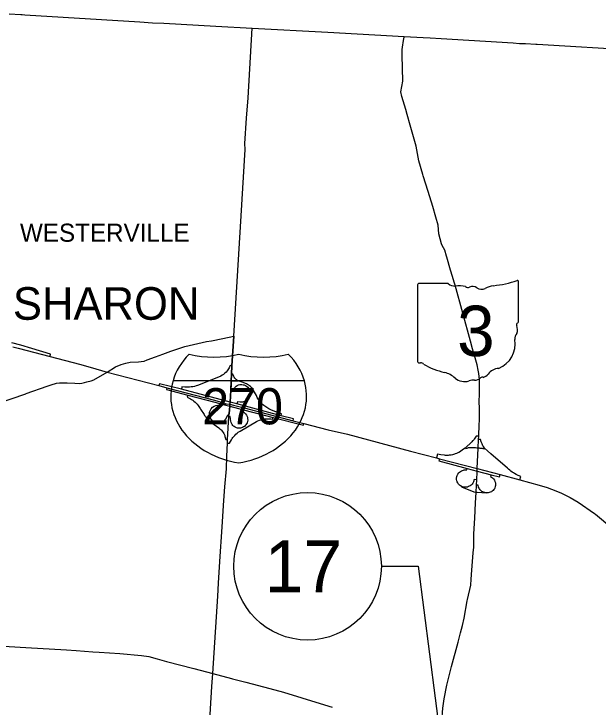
# Model space of a CAD drawing. Extents: x -1146 to -445, y -1283 to -822.
# Drawn here: x -863.1 to -822.78, y -948.44 to -900.58 of the extents above; entities that cross this region are included whole.
import ezdxf

# ---------------------------------------------------------------- set-up
doc = ezdxf.new("R2010")
doc.units = 0
for name, color, linetype in [('Default', 7, 'Continuous'), ('GM_X_Corporation_Text', 7, 'Continuous'), ('GM_X_County', 7, 'Continuous'), ('GM_X_Interchange_Ramps', 7, 'Continuous'), ('GM_X_Interstate_Route', 7, 'Continuous'), ('GM_X_Interstate_Shield', 7, 'Continuous'), ('GM_X_State_Route', 7, 'Continuous'), ('GM_X_State_Shield', 7, 'Continuous'), ('GM_X_Township', 7, 'Continuous'), ('GM_X_Township_Text', 7, 'Continuous')]:
    doc.layers.add(name, color=color, linetype=linetype)

msp = doc.modelspace()

# ---------------------------------------------------------------- linework, layer by layer
at = {"layer": 'Default'}
msp.add_lwpolyline([(-837.735, -938.717), (-835.188, -938.717), (-833.622, -950.863)], dxfattribs=at)
msp.add_circle((-842.83, -938.717), 5.094, dxfattribs=at)
at = {"layer": 'GM_X_County'}
msp.add_lwpolyline([(-863.427, -900.578), (-862.623, -900.623), (-862.528, -900.628), (-862.344, -900.639), (-854.414, -901.127), (-853.529, -901.186), (-852.746, -901.23), (-849.162, -901.431), (-846.653, -901.557), (-841.434, -901.832), (-836.157, -902.132), (-834.842, -902.215), (-834.367, -902.243), (-833.605, -902.289), (-828.634, -902.589), (-828.197, -902.613), (-827.798, -902.635), (-827.073, -902.676), (-826.986, -902.681), (-820.114, -903.073)], dxfattribs=at)
at = {"layer": 'GM_X_Interchange_Ramps'}
for points in [[(-860.593, -924.234), (-860.567, -924.06), (-861.86, -923.684), (-862.612, -923.457), (-863.25, -923.291)], [(-848.052, -924.87), (-848.177, -924.863), (-848.209, -924.943), (-848.243, -925.012), (-848.287, -925.09), (-848.329, -925.154), (-848.387, -925.232), (-848.452, -925.307), (-848.535, -925.388), (-848.626, -925.463), (-848.714, -925.523), (-848.826, -925.586), (-848.981, -925.652), (-850.419, -926.232), (-850.519, -926.264), (-850.629, -926.293), (-850.753, -926.319), (-850.854, -926.335), (-850.979, -926.348), (-851.067, -926.354), (-851.178, -926.355), (-851.292, -926.352), (-851.498, -926.335), (-851.537, -926.479)], [(-844.655, -928.316), (-844.621, -928.179), (-845.024, -928.046), (-845.317, -927.928), (-845.507, -927.841), (-845.712, -927.716), (-845.786, -927.663), (-845.853, -927.609), (-845.93, -927.541), (-846.005, -927.467), (-846.056, -927.411), (-846.115, -927.34), (-846.162, -927.278), (-846.216, -927.2), (-846.261, -927.127), (-846.3, -927.058), (-846.332, -926.993), (-846.359, -926.935), (-846.566, -926.57), (-846.596, -926.517), (-846.636, -926.456), (-846.679, -926.402), (-846.737, -926.338), (-846.78, -926.297), (-846.829, -926.256), (-846.885, -926.215), (-846.933, -926.184), (-846.986, -926.155), (-847.047, -926.125), (-847.103, -926.103), (-847.167, -926.083), (-847.592, -925.91), (-847.657, -925.879), (-847.706, -925.85), (-847.756, -925.812), (-847.802, -925.771), (-847.842, -925.727), (-847.885, -925.669), (-847.912, -925.622), (-847.989, -925.457), (-848.085, -925.452)], [(-847.592, -925.91), (-847.603, -925.937), (-848.009, -925.932), (-848.102, -925.932)], [(-843.829, -928.663), (-843.799, -928.545), (-844.655, -928.316), (-847.713, -927.5), (-848.18, -927.375), (-851.537, -926.479), (-853.054, -926.112), (-853.088, -926.242)], [(-852.537, -926.385), (-852.571, -926.513), (-851.09, -926.899), (-849.224, -927.385), (-848.65, -927.535), (-848.202, -927.652), (-847.244, -927.903), (-845.211, -928.435), (-843.118, -928.982), (-843.085, -928.854)], [(-848.124, -926.56), (-847.985, -926.569), (-847.906, -926.442), (-847.868, -926.389), (-847.813, -926.326), (-847.761, -926.276), (-847.692, -926.232), (-847.607, -926.195), (-847.51, -926.17), (-847.442, -926.162), (-847.374, -926.162), (-847.27, -926.177), (-847.197, -926.198), (-847.109, -926.238), (-847.038, -926.285), (-846.961, -926.354), (-846.887, -926.451), (-846.836, -926.554), (-846.811, -926.639), (-846.797, -926.743), (-846.802, -926.859), (-846.826, -926.961), (-846.865, -927.054), (-846.914, -927.132), (-846.96, -927.188), (-847.031, -927.253), (-847.104, -927.302), (-847.167, -927.333), (-847.252, -927.362), (-847.332, -927.377), (-847.478, -927.38), (-847.675, -927.366), (-847.713, -927.5)], [(-851.09, -926.899), (-851.129, -927.048), (-850.997, -927.103), (-850.912, -927.151), (-850.832, -927.201), (-850.754, -927.255), (-850.679, -927.313), (-850.596, -927.385), (-850.527, -927.45), (-850.453, -927.53), (-850.383, -927.614), (-850.338, -927.673), (-850.286, -927.749), (-850.244, -927.816), (-850.211, -927.874), (-849.975, -928.231), (-849.933, -928.301), (-849.885, -928.372), (-849.842, -928.431), (-849.777, -928.51), (-849.714, -928.58), (-849.654, -928.641), (-849.581, -928.707), (-849.515, -928.761), (-849.436, -928.821), (-849.37, -928.865), (-849.273, -928.923), (-848.947, -929.165), (-848.883, -929.217), (-848.825, -929.271), (-848.772, -929.327), (-848.716, -929.395), (-848.662, -929.472), (-848.615, -929.551), (-848.574, -929.633), (-848.551, -929.687), (-848.53, -929.744), (-848.509, -929.814), (-848.476, -929.954), (-848.351, -929.961)], [(-847.244, -927.903), (-847.283, -928.039), (-847.217, -928.09), (-847.171, -928.132), (-847.106, -928.2), (-847.052, -928.273), (-847.018, -928.335), (-846.986, -928.42), (-846.967, -928.511), (-846.963, -928.621), (-846.977, -928.721), (-847.01, -928.821), (-847.044, -928.887), (-847.082, -928.943), (-847.136, -929.006), (-847.19, -929.053), (-847.241, -929.088), (-847.312, -929.126), (-847.382, -929.152), (-847.456, -929.169), (-847.566, -929.177), (-847.655, -929.168), (-847.74, -929.146), (-847.827, -929.11), (-847.891, -929.07), (-847.94, -929.032), (-847.984, -928.989), (-848.028, -928.937), (-848.066, -928.878), (-848.103, -928.798), (-848.129, -928.694), (-848.144, -928.616), (-848.155, -928.532), (-848.167, -928.37), (-848.26, -928.365)], [(-848.365, -930.211), (-848.214, -930.22), (-848.087, -929.982), (-848.037, -929.902), (-847.979, -929.82), (-847.921, -929.748), (-847.855, -929.675), (-847.782, -929.604), (-847.698, -929.531), (-847.61, -929.466), (-847.486, -929.387), (-846.363, -928.723), (-846.258, -928.674), (-846.137, -928.627), (-846.048, -928.599), (-845.952, -928.574), (-845.853, -928.553), (-845.751, -928.538), (-845.658, -928.53), (-845.573, -928.527), (-845.48, -928.527), (-845.366, -928.535), (-845.24, -928.551), (-845.211, -928.435)], [(-831.012, -929.729), (-831.202, -929.72), (-831.287, -929.867), (-831.33, -929.932), (-831.361, -929.974), (-831.399, -930.02), (-831.437, -930.064), (-831.495, -930.122), (-831.957, -930.552), (-832.128, -930.68), (-832.272, -930.782), (-832.394, -930.851), (-832.45, -930.88), (-832.55, -930.926), (-832.638, -930.961), (-832.694, -930.98), (-832.768, -931.002), (-832.839, -931.019), (-832.917, -931.035), (-832.983, -931.045), (-833.062, -931.054), (-833.137, -931.059), (-833.215, -931.06), (-833.302, -931.058), (-833.378, -931.052), (-833.638, -931.027), (-833.862, -930.984), (-833.928, -931.237)], [(-828.18, -932.756), (-828.115, -932.51), (-828.293, -932.437), (-828.436, -932.367), (-828.54, -932.31), (-828.624, -932.26), (-828.7, -932.21), (-828.791, -932.144), (-828.873, -932.079), (-828.955, -932.008), (-829.021, -931.945), (-830.181, -930.954), (-830.403, -930.752), (-830.609, -930.55), (-830.682, -930.451), (-830.723, -930.387), (-830.752, -930.335), (-830.786, -930.268), (-830.814, -930.204), (-830.843, -930.121), (-830.891, -929.956), (-831.024, -929.95)], [(-831.057, -930.569), (-831.159, -930.571), (-831.248, -930.547), (-831.358, -930.532), (-831.486, -930.526), (-831.627, -930.531), (-831.697, -930.541), (-831.743, -930.547), (-831.793, -930.557), (-831.848, -930.572), (-831.92, -930.596), (-831.957, -930.552)], [(-830.609, -930.55), (-830.671, -930.621), (-830.718, -930.604), (-830.768, -930.59), (-830.815, -930.581), (-830.873, -930.574), (-830.925, -930.572), (-830.972, -930.568), (-831.057, -930.569)], [(-833.732, -931.288), (-833.772, -931.439), (-831.815, -931.956), (-831.132, -932.136), (-830.165, -932.392), (-829.583, -932.546), (-829.54, -932.384)], [(-831.159, -932.739), (-831.33, -932.734), (-831.389, -932.892), (-831.431, -932.973), (-831.479, -933.042), (-831.539, -933.104), (-831.616, -933.164), (-831.712, -933.215), (-831.798, -933.244), (-831.88, -933.258), (-832.003, -933.259), (-832.099, -933.241), (-832.171, -933.219), (-832.273, -933.164), (-832.348, -933.105), (-832.412, -933.037), (-832.467, -932.956), (-832.499, -932.889), (-832.525, -932.814), (-832.54, -932.732), (-832.544, -932.634), (-832.528, -932.522), (-832.502, -932.44), (-832.464, -932.362), (-832.396, -932.266), (-832.338, -932.209), (-832.286, -932.168), (-832.211, -932.124), (-832.13, -932.091), (-832.063, -932.073), (-832.012, -932.065), (-831.943, -932.06), (-831.841, -932.058), (-831.815, -931.956)], [(-830.165, -932.392), (-830.196, -932.509), (-830.061, -932.614), (-829.99, -932.688), (-829.937, -932.766), (-829.895, -932.858), (-829.87, -932.945), (-829.86, -933.031), (-829.863, -933.126), (-829.879, -933.214), (-829.905, -933.292), (-829.938, -933.358), (-829.979, -933.42), (-830.031, -933.48), (-830.088, -933.53), (-830.145, -933.57), (-830.218, -933.608), (-830.3, -933.631), (-830.356, -933.641), (-830.41, -933.644), (-830.475, -933.64), (-830.59, -933.628), (-830.68, -933.605), (-830.736, -933.58), (-830.806, -933.542), (-830.874, -933.484), (-830.916, -933.437), (-830.963, -933.372), (-830.993, -933.315), (-831.022, -933.242), (-831.053, -933.112), (-831.175, -933.109)], [(-831.198, -933.621), (-831.321, -933.588), (-832.183, -933.256), (-832.171, -933.219)], [(-830.475, -933.64), (-830.478, -933.666), (-831.133, -933.623), (-831.198, -933.621)]]:
    msp.add_lwpolyline(points, dxfattribs=at)
at = {"layer": 'GM_X_Interstate_Route'}
for points in [[(-863.169, -923.566), (-862.813, -923.649), (-860.593, -924.234), (-858.566, -924.759), (-857.841, -924.971)], [(-857.841, -924.971), (-856.669, -925.314)], [(-856.669, -925.314), (-853.088, -926.242)], [(-853.088, -926.242), (-852.537, -926.385)], [(-852.537, -926.385), (-849.248, -927.236), (-848.69, -927.41)], [(-848.69, -927.41), (-848.437, -927.49), (-848.191, -927.531)], [(-848.191, -927.531), (-847.941, -927.593)], [(-847.941, -927.593), (-847.206, -927.773), (-843.829, -928.663)], [(-843.829, -928.663), (-843.085, -928.854)], [(-843.085, -928.854), (-841.4, -929.288), (-840.085, -929.603), (-835.715, -930.767), (-833.928, -931.237), (-833.732, -931.288)], [(-833.732, -931.288), (-831.125, -931.966)], [(-831.125, -931.966), (-829.54, -932.384)], [(-829.54, -932.384), (-828.18, -932.756)], [(-828.18, -932.756), (-828.18, -932.756), (-826.848, -933.11), (-826.292, -933.267), (-825.7, -933.505), (-825.311, -933.662), (-824.714, -933.96), (-824.143, -934.284), (-823.019, -935.068)], [(-823.019, -935.068), (-822.957, -935.112), (-822.398, -935.578), (-821.906, -936.013), (-821.402, -936.526), (-820.942, -937.106), (-820.2, -938.171), (-819.704, -939.027), (-819.448, -939.58), (-819.333, -939.832), (-819.178, -940.203), (-819.059, -940.53), (-818.891, -941.046), (-818.788, -941.415), (-818.67, -941.884), (-818.633, -942.053), (-818.569, -942.406), (-818.474, -942.902), (-818.421, -943.397), (-818.396, -943.686), (-818.379, -944.45)]]:
    msp.add_lwpolyline(points, dxfattribs=at)
at = {"layer": 'GM_X_Interstate_Shield'}
msp.add_line((-843.052, -925.91), (-852.117, -925.91), dxfattribs=at)
msp.add_line((-843.052, -925.91), (-852.117, -925.91), dxfattribs=at)
for centre, start_param, end_param in [((-846.412, -926.981), 2.47259, 2.911027), ((-849.297, -919.591), 4.415841, 5.008937), ((-845.872, -919.591), 4.415841, 5.008937), ((-848.756, -926.981), 0.230566, 0.669003), ((-846.412, -926.981), 2.911027, 4.511031), ((-848.756, -926.981), 4.913747, 6.513751)]:
    msp.add_ellipse(centre, major_axis=(5.859, 0), ratio=0.8, start_param=start_param, end_param=end_param, dxfattribs=at)
at = {"layer": 'GM_X_State_Route'}
for points in [[(-835.96, -907.522), (-835.961, -907.517), (-836.051, -907.186), (-836.314, -906.287), (-836.387, -905.957), (-836.252, -905.223), (-836.308, -903.42), (-836.297, -903.034), (-836.287, -902.866), (-836.217, -902.406), (-836.171, -902.192), (-836.157, -902.132)], [(-834.499, -912.834), (-834.853, -911.767), (-834.878, -911.676), (-835.162, -910.728), (-835.33, -909.711), (-835.562, -908.91), (-835.749, -908.253), (-835.96, -907.522)], [(-833.981, -914.609), (-834.19, -913.876), (-834.499, -912.834)], [(-833.243, -917.316), (-833.352, -916.896), (-833.55, -916.563), (-833.581, -916.458), (-833.768, -915.771), (-833.819, -915.174), (-833.981, -914.609)], [(-832.717, -919.09), (-832.833, -918.702), (-832.961, -918.265), (-833.227, -917.375), (-833.243, -917.316)], [(-830.965, -926.217), (-830.964, -926.105), (-830.973, -925.83), (-831.017, -925.405), (-831.052, -925.171), (-831.136, -924.813), (-831.225, -924.481), (-831.44, -923.704), (-831.583, -923.162), (-832.649, -919.316), (-832.717, -919.09)], [(-858.411, -926.065), (-858.225, -926.037), (-858.054, -925.973), (-857.768, -925.916), (-857.583, -925.837), (-856.669, -925.314), (-856.077, -924.952), (-855.699, -924.788), (-855.371, -924.695), (-855.079, -924.624), (-854.508, -924.602), (-854.315, -924.581), (-854.101, -924.545), (-853.894, -924.467), (-853.331, -924.253), (-852.817, -924.069), (-852.256, -923.869), (-851.302, -923.537), (-849.799, -923.206), (-849.472, -923.142), (-848.685, -922.989), (-847.91, -922.826)], [(-847.91, -922.826), (-848.052, -924.87), (-848.085, -925.452), (-848.102, -925.932), (-848.108, -926.112)], [(-867.897, -927.478), (-866.981, -927.517), (-865.689, -927.59), (-865.153, -927.621), (-864.988, -927.618), (-864.818, -927.605), (-864.673, -927.582), (-864.317, -927.495), (-862.285, -926.801), (-862.241, -926.786), (-860.805, -926.288), (-860.536, -926.18), (-860.158, -926.073), (-859.951, -926.044), (-859.423, -926.051), (-858.896, -926.073), (-858.553, -926.087), (-858.411, -926.065)], [(-848.108, -926.112), (-848.124, -926.56), (-848.18, -927.375), (-848.191, -927.531), (-848.202, -927.652), (-848.249, -928.176)], [(-830.973, -927.703), (-830.979, -927.443), (-830.969, -926.712), (-830.965, -926.217)], [(-848.249, -928.176), (-848.348, -928.315), (-848.491, -928.557), (-848.608, -928.687), (-848.715, -928.754), (-848.831, -928.799), (-849.028, -928.821), (-849.122, -928.808), (-849.306, -928.714), (-849.386, -928.669), (-849.494, -928.566), (-849.574, -928.436), (-849.61, -928.257), (-849.592, -928.064), (-849.534, -927.93), (-849.48, -927.849), (-849.395, -927.738), (-849.274, -927.657), (-849.154, -927.612), (-849.033, -927.594), (-848.8, -927.567), (-848.65, -927.535), (-848.437, -927.49)], [(-830.969, -928.649), (-830.958, -928.356), (-830.973, -927.703)], [(-831.135, -932.187), (-831.132, -932.136), (-831.125, -931.966), (-831.057, -930.569), (-831.024, -929.95), (-831.012, -929.729), (-830.98, -928.919)], [(-830.98, -928.919), (-830.969, -928.649)], [(-831.292, -935.382), (-831.242, -934.328), (-831.198, -933.621), (-831.175, -933.109), (-831.159, -932.739), (-831.135, -932.187)], [(-831.784, -941.01), (-831.572, -940.025), (-831.535, -939.594), (-831.485, -938.989), (-831.396, -937.784), (-831.355, -937.388), (-831.344, -936.466), (-831.292, -935.382)], [(-832.142, -942.804), (-832.016, -942.304), (-831.804, -941.103), (-831.784, -941.01)], [(-832.441, -943.953), (-832.27, -943.311), (-832.142, -942.804)], [(-872.919, -943.732), (-872.667, -943.746), (-871.248, -943.798), (-870.354, -943.844), (-867.222, -944.02), (-866.293, -944.081), (-863.431, -944.259), (-862.283, -944.317), (-859.466, -944.485), (-858.806, -944.532), (-857.647, -944.608)], [(-833.572, -949.535), (-833.567, -949.437), (-833.501, -948.499), (-833.405, -947.866), (-833.225, -946.919), (-832.89, -945.628), (-832.441, -943.953)], [(-857.647, -944.608), (-857.216, -944.636), (-855.785, -944.734), (-854.29, -944.868), (-853.784, -944.951), (-853.216, -945.105), (-852.563, -945.283), (-850.671, -945.762), (-849.374, -946.107), (-848.081, -946.453)], [(-848.081, -946.453), (-848.002, -946.474), (-847.097, -946.714), (-845.436, -947.146), (-844.48, -947.406), (-841.955, -948.181), (-841.13, -948.437)]]:
    msp.add_lwpolyline(points, dxfattribs=at)
at = {"layer": 'GM_X_State_Shield'}
for p, q in [((-835.238, -919.293), (-835.238, -924.576)), ((-833.131, -919.202), (-835.169, -919.202)), ((-828.277, -921.834), (-828.277, -919.071)), ((-828.277, -921.834), (-828.277, -921.834))]:
    msp.add_line(p, q, dxfattribs=at)
for centre, radius, start, end in [((-835.158, -919.281), 0.0806, 98.1301, 188.1301), ((-832.645, -918.588), 0.782, 231.6195, 271.1119), ((-832.386, -922.168), 2.808, 80.4867, 94.9883), ((-829.815, -920.815), 1.485, 97.3462, 120.7689), ((-830.756, -911.999), 7.382, 275.8445, 288.9065), ((-828.354, -919.059), 0.0775, 351.8621, 97.738), ((-831.748, -919.254), 0.226, 219.7921, 297.1024), ((-831.417, -919.865), 0.469, 54.4667, 119.1411), ((-830.811, -919.027), 0.564, 233.8562, 294.8282), ((-828.295, -922.037), 0.12, 107.944, 210.337), ((-829.058, -922.387), 0.72, 340.033, 23.6496), ((-828.359, -921.845), 0.0829, 289.6038, 7.7341), ((-827.999, -922.991), 0.524, 136.8065, 186.9296), ((-830.343, -923.343), 1.846, 292.3089, 8.9858), ((-835.157, -924.587), 0.0814, 171.9584, 258.3066), ((-835.145, -924.047), 0.621, 267.339, 280.6039), ((-835.018, -924.881), 0.224, 29.7484, 93.2717), ((-832.191, -920.134), 5.331, 240.4129, 257.1985), ((-829.564, -926.059), 1.011, 94.4031, 142.5768), ((-833.781, -926.949), 1.668, 47.1842, 75.836), ((-830.845, -925.088), 0.597, 282.8732, 323.2771), ((-831.977, -924.907), 1.058, 230.7004, 286.2918), ((-831.365, -926.733), 0.87, 85.6951, 111.2099), ((-831.288, -925.302), 0.564, 268.777, 315.5493), ((-830.778, -925.814), 0.159, 65.7517, 132.6484)]:
    msp.add_arc(centre, radius, start, end, dxfattribs=at)
at = {"layer": 'GM_X_Township'}
msp.add_lwpolyline([(-849.646, -950.492), (-849.428, -947.009), (-849.374, -946.107), (-849.332, -945.403), (-849.029, -940.785), (-848.976, -939.874), (-848.883, -938.372), (-848.717, -935.99), (-848.599, -934.172), (-848.53, -933.24), (-848.424, -931.98), (-848.404, -931.109), (-848.365, -930.211), (-848.351, -929.961), (-848.26, -928.365), (-848.249, -928.176), (-848.202, -927.652), (-848.191, -927.531), (-848.18, -927.375), (-848.124, -926.56), (-848.102, -925.932), (-848.085, -925.452), (-848.052, -924.87), (-847.91, -922.826), (-847.411, -914.514), (-847.129, -909.948), (-847.161, -909.531), (-847.041, -907.781), (-846.93, -906.374), (-846.653, -901.557)], dxfattribs=at)

# ---------------------------------------------------------------- texts
at = {"layer": 'Default'}
msp.add_text('17', height=3.6, dxfattribs=at).set_placement((-845.799, -940.517))
at = {"layer": 'GM_X_Corporation_Text'}
msp.add_text('WESTERVILLE', height=1.25, rotation=0, dxfattribs=at).set_placement((-862.679, -916.311))
at = {"layer": 'GM_X_Interstate_Shield'}
msp.add_text('270', height=2.5, dxfattribs=at).set_placement((-850.109, -928.917))
at = {"layer": 'GM_X_State_Shield'}
msp.add_text('3', height=3.48, dxfattribs=at).set_placement((-832.508, -924.203))
at = {"layer": 'GM_X_Township_Text'}
msp.add_text('SHARON', height=2.25, rotation=0, dxfattribs=at).set_placement((-863.168, -921.696))

doc.saveas('drawing.dxf')
